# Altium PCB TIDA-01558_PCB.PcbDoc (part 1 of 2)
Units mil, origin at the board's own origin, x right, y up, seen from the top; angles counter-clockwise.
Board outline 2362.2 x 2362.2 mil, 2 copper layers (Top Layer, Bottom Layer), stack 64.8 mil thick; 83 components, 39 nets, 200 pads, 58 vias.
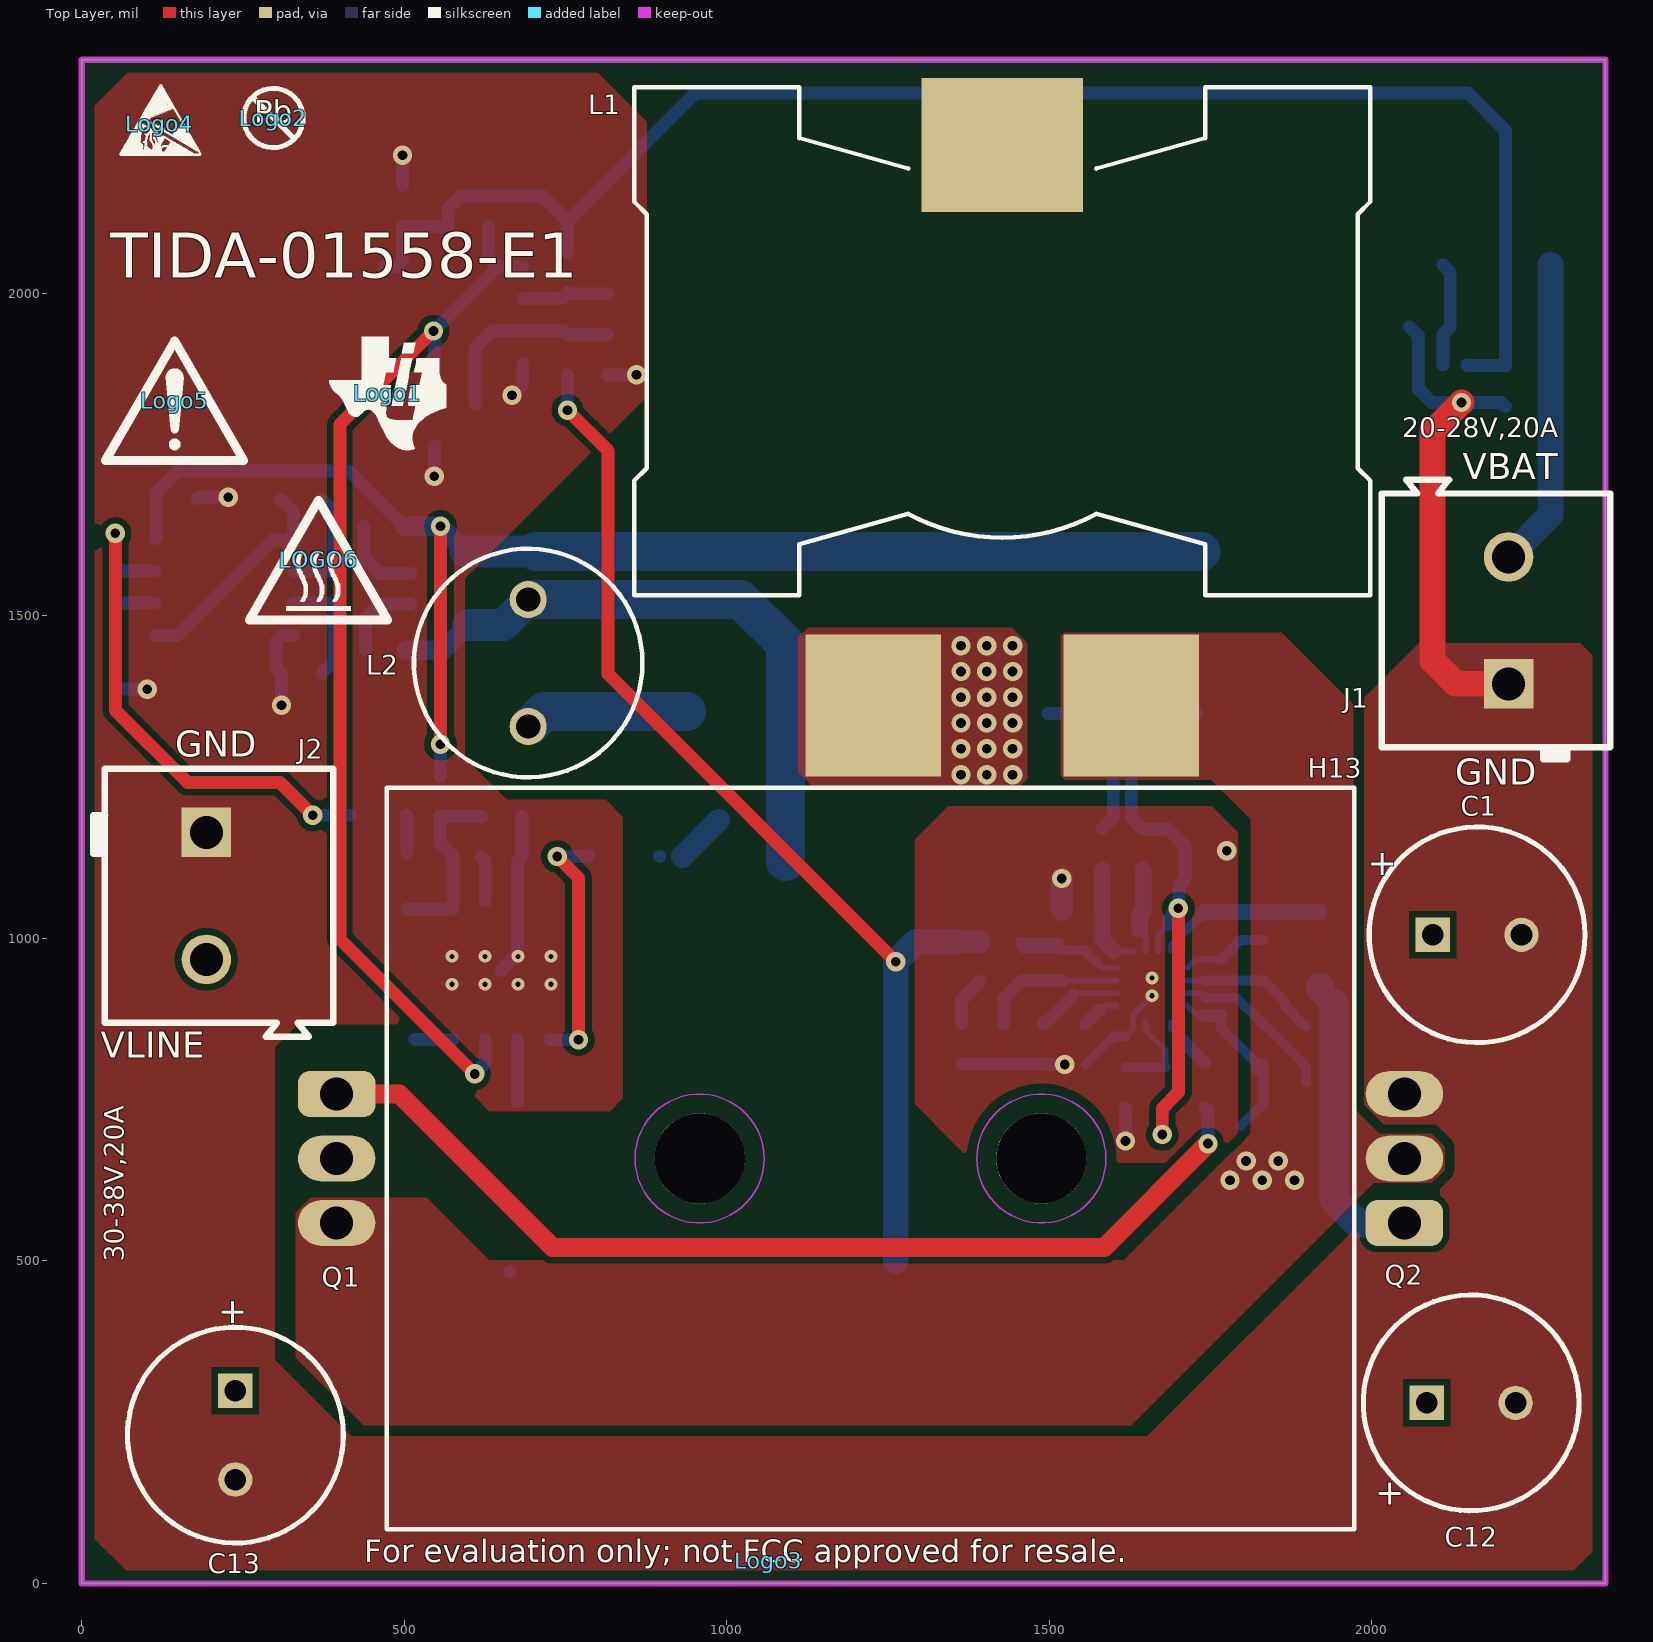
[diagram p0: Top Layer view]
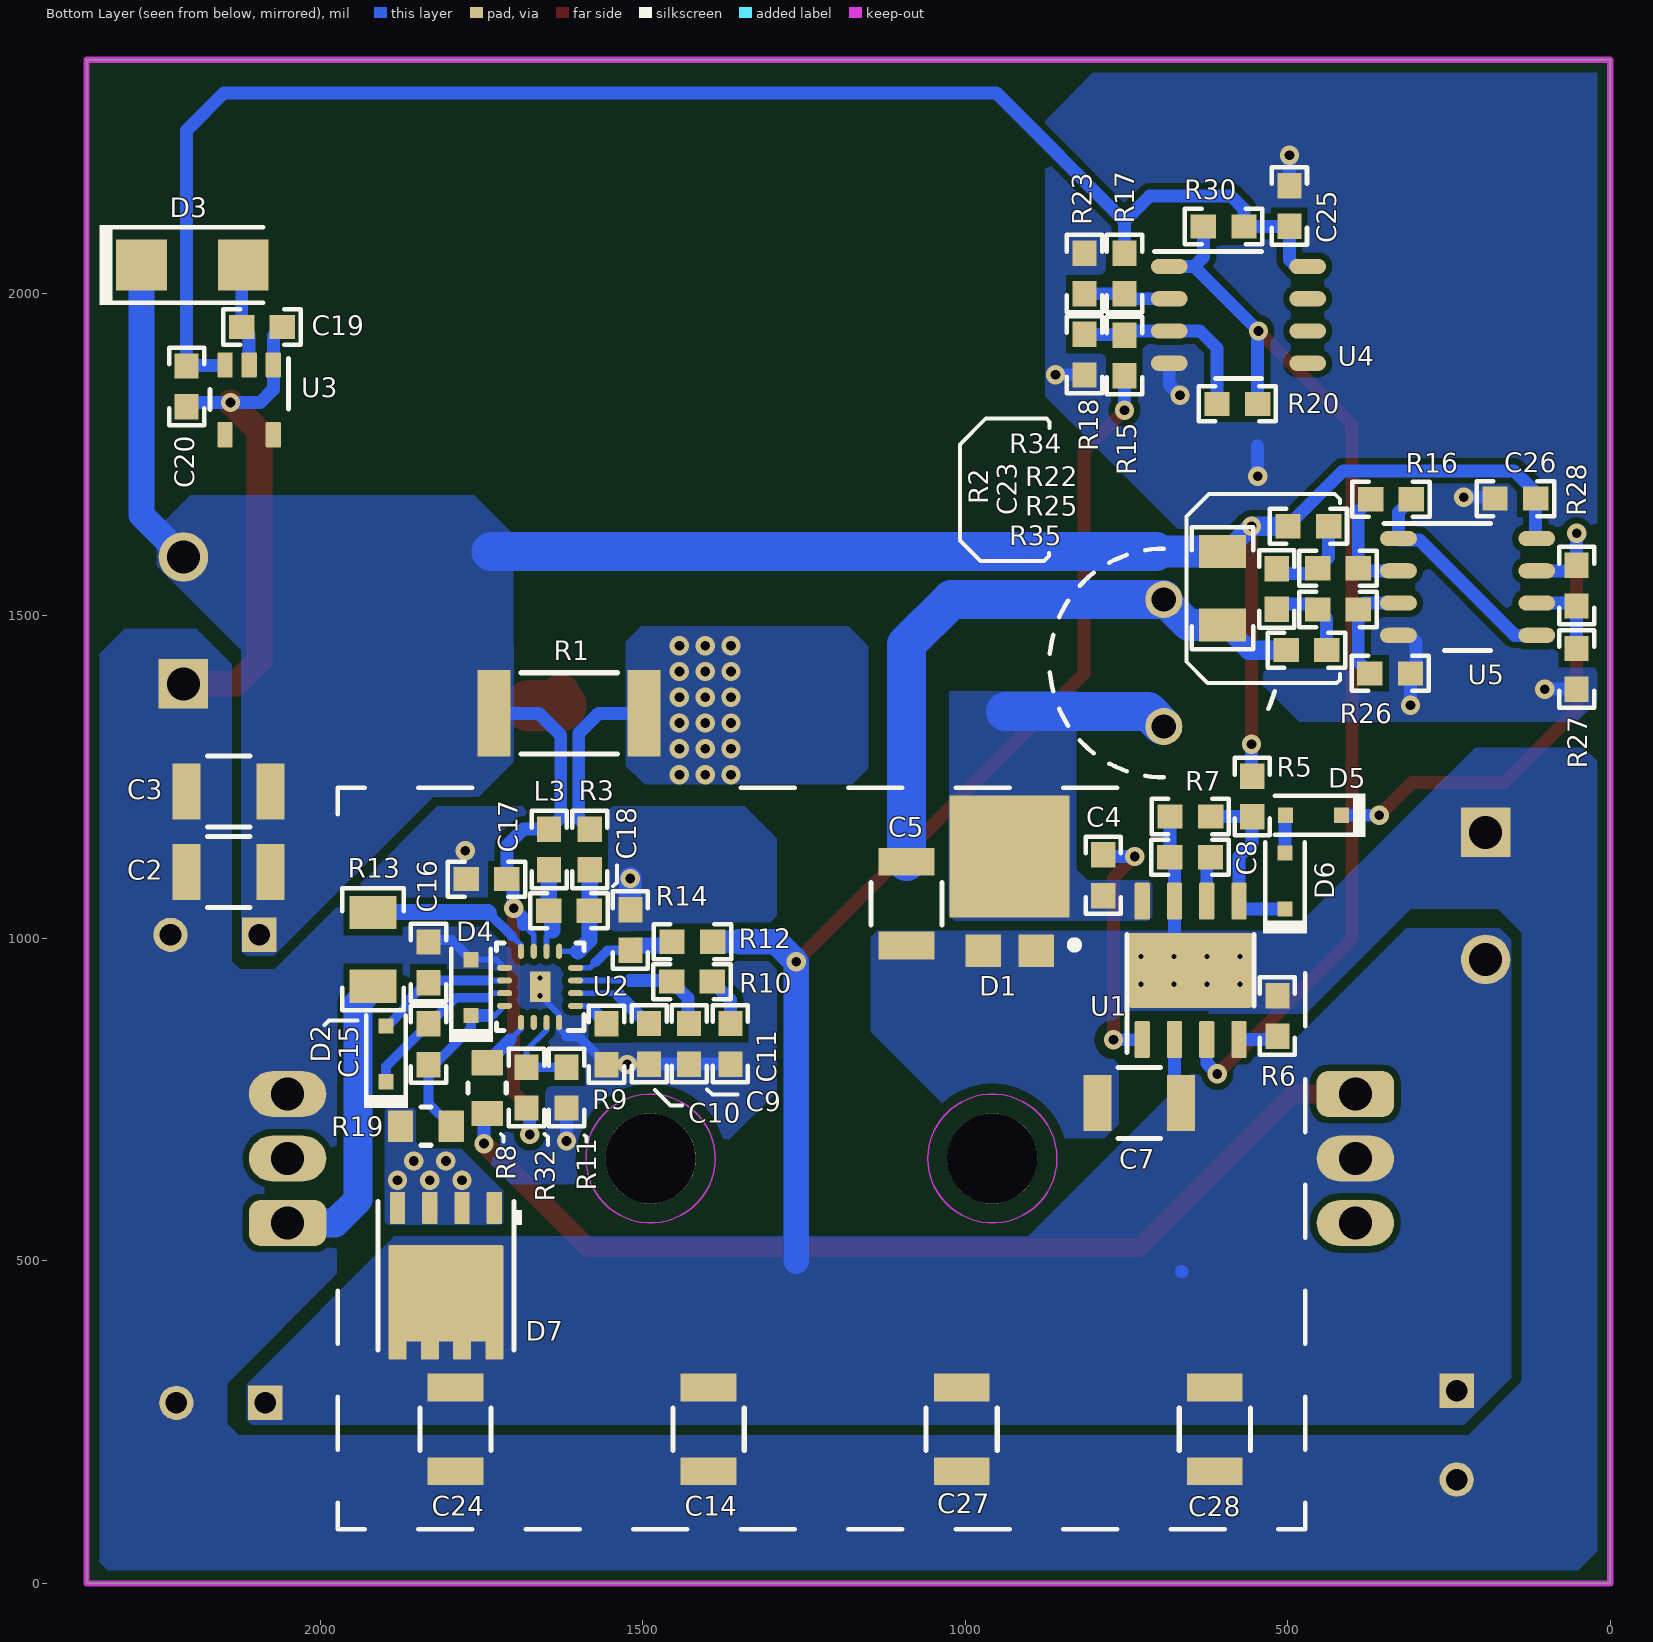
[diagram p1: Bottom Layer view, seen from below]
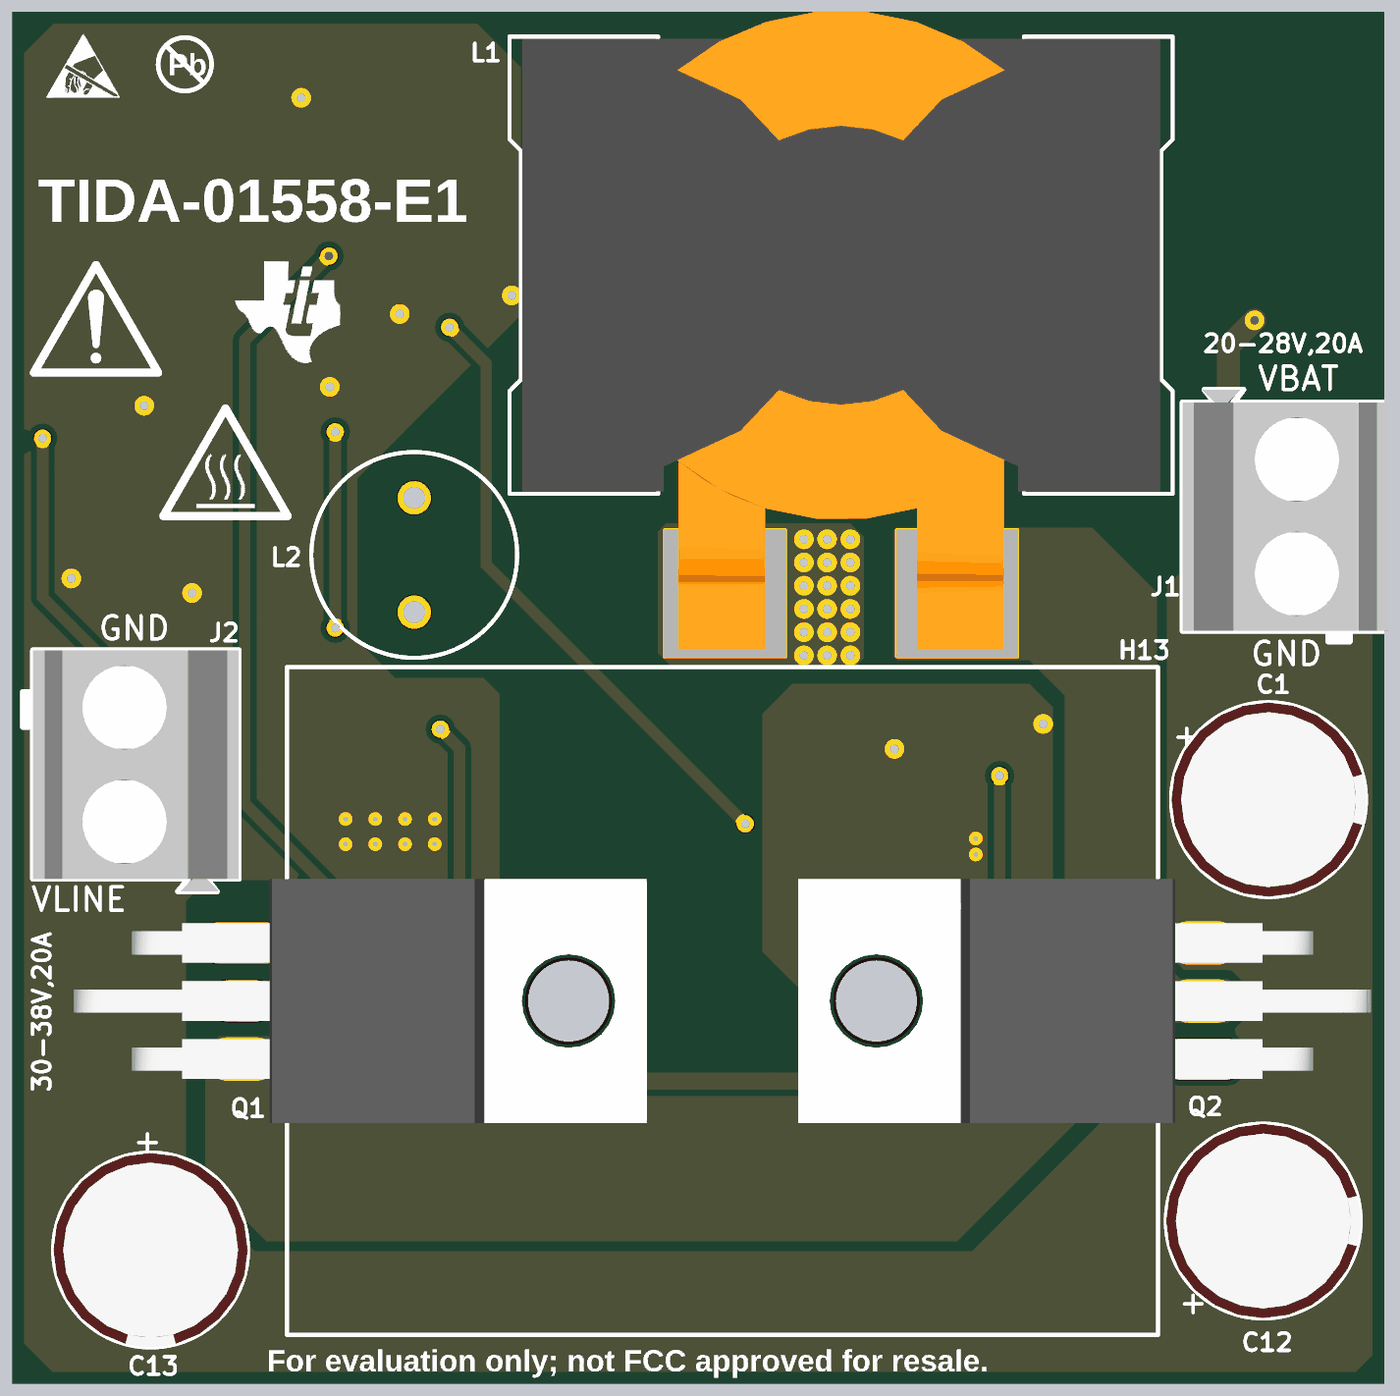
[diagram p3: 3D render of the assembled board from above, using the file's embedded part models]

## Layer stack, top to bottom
Top Solder: solder mask 0.4, Solder Resist, Dk 3.5
Top Layer: signal copper 2.8
Dielectric1: core 59.2, FR-4 High Tg, Dk 4.8
Bottom Layer: signal copper 2.8
Bottom Solder: solder mask 0.4, Solder Resist, Dk 3.5

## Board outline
0,0 0,2362.2 2362.2,2362.2 2362.2,0

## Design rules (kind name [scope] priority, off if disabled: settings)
AcuteAngle [All] p1: minimum=4.50000000000000E+0001 checktracksonly=FALSE
AssemblyTestPointUsage [All] p1: valid=2
Clearance Clearance_Keepouts [((IsTrack Or IsArc) And Not InPoly) And IsFree and IsKeepOut vs ((IsTrack Or IsArc) And Not InPoly) And IsFree and IsKeepOut] p1: gap=590.55 ignorepadtopadclearanceinfootprint=FALSE except(0: Arc-Hole Track-Hole SMDPad-Hole THPad-Hole Via-Hole Fill-Hole Poly-Hole Region-Hole Text-Hole)
Clearance Clearance_BoardEdge_MountingHoles [OnCopper and InComponentClass('Mounting Holes') vs IsKeepOut] p2: gap=40 ignorepadtopadclearanceinfootprint=FALSE except(0: Arc-Hole Track-Hole SMDPad-Hole THPad-Hole Via-Hole Fill-Hole Poly-Hole Region-Hole Text-Hole)
Clearance Clearance_BoardEdge_Poly [OnCopper and InPoly vs IsKeepOut] p3: gap=15 ignorepadtopadclearanceinfootprint=FALSE except(0: Arc-Hole Track-Hole SMDPad-Hole THPad-Hole Via-Hole Fill-Hole Poly-Hole Region-Hole Text-Hole)
Clearance Clearance_BoardEdge [OnCopper and Not InComponentClass('Logo') and not InComponentClass('FiducialMark') and not InRegion(1000,500,4000,800) and Not IsKeepout vs IsKeepOut] p4: gap=15 ignorepadtopadclearanceinfootprint=FALSE except(0: Arc-Hole Track-Hole SMDPad-Hole THPad-Hole Via-Hole Fill-Hole Poly-Hole Region-Hole Text-Hole)
Clearance Clearance_Poly [InPolygon] p5: gap=10 ignorepadtopadclearanceinfootprint=FALSE except(0: Arc-Hole Track-Hole SMDPad-Hole THPad-Hole Via-Hole Fill-Hole Poly-Hole Region-Hole Text-Hole; 15: Poly-Poly)
Clearance [All] p6: gap=7.87 ignorepadtopadclearanceinfootprint=FALSE except(0: Arc-Hole Track-Hole SMDPad-Hole THPad-Hole Via-Hole Fill-Hole Poly-Hole Region-Hole Text-Hole)
ComponentClearance ComponentClearance_MountingHoles_FiducialMarks [InComponentClass('Mounting Holes') vs InComponentClass('FiducialMark')] p1: gap=50 collisioncheckmode=3 verticalgap=10 showdistances=FALSE
ComponentClearance ComponentClearance_Shunt [InComponentClass('Header') vs InComponentClass('Shunt')] p2: gap=0 collisioncheckmode=3 verticalgap=0 showdistances=FALSE
ComponentClearance ComponentClearance_Logo [InComponentClass('Logo')] p3: gap=50 collisioncheckmode=3 verticalgap=10 showdistances=FALSE
ComponentClearance ComponentClearance_ScrewToNut [(HasFootprint('NY PMS 440 0025 PH')) vs (HasFootprint('Keystone_1902C'))] p4: gap=5 collisioncheckmode=3 verticalgap=10 showdistances=FALSE
ComponentClearance ComponentClearance_MountingHoles [InComponentClass('Mounting Holes')] p5: gap=250 collisioncheckmode=3 verticalgap=100000 showdistances=FALSE
ComponentClearance ComponentClearance_SmallPassives [HasFootprint('0201*') or HasFootprint('0402*') or HasFootprint('0508') or HasFootprint('0603*') or HasFootprint('0612') or HasFootprint('0805*') or HasFootprint('0815*') or HasFootprint('0830*') or HasFootprint('1206*') or HasFootprint('1210*') or HasFootprint('1808*') or HasFootprint('1812*') or HasFootprint('1825*') or HasFootprint('2010*') or HasFootprint('2220*') or HasFootprint('2225*') or HasFootprint('2512*') or HasFootprint('2728*') or HasFootprint('3518*') vs HasFootprint('0201*') or HasFootprint('0402*') or HasFootprint('0508') or HasFootprint('0603*') or HasFootprint('0612') or HasFootprint('0805*') or HasFootprint('0815*') or HasFootprint('0830*') or HasFootprint('1206*') or HasFootprint('1210*') or HasFootprint('1808*') or HasFootprint('1812*') or HasFootprint('1825*') or HasFootprint('2010*') or HasFootprint('2220*') or HasFootprint('2225*') or HasFootprint('2512*') or HasFootprint('2728*') or HasFootprint('3518*')] p6: gap=10 collisioncheckmode=3 verticalgap=10 showdistances=FALSE
ComponentClearance ComponentClearance_THtoSMT [IsThruComponent vs IsSMTComponent] p7: gap=10 collisioncheckmode=3 verticalgap=10 showdistances=FALSE
ComponentClearance ComponentClearance_THtoTH [IsThruComponent vs IsThruComponent] p8: gap=10 collisioncheckmode=3 verticalgap=10 showdistances=FALSE
ComponentClearance [All] p9: gap=10 collisioncheckmode=3 verticalgap=10 showdistances=FALSE
DiffPairsRouting [All] p1: maxlimit=100 minlimit=10 mostfreqgap=10 toplayer_minwidth=15 toplayer_maxwidth=15 toplayer_prefwidth=15 bottomlayer_minwidth=15 bottomlayer_maxwidth=15 bottomlayer_prefwidth=15 maxuncoupledlength=1000
FabricationTestPointUsage TestPointUsage [All] p1: valid=2 allowmultiple=FALSE
FabricationTestpoint Testpoint [All] p1: side=3 testpointundercomponent=TRUE minsize=40 maxsize=100 preferedsize=60 minholesize=0 maxholesize=40 preferedholesize=32 testpointgrid=1 allowsidetop=TRUE allowsidebottom=TRUE usegrid=TRUE gridtolerance=0.01
FanoutControl Fanout_LCC [IsLCC] p1: bgadir=Out bgaviamode=Centered fanoutstyle=Auto fanoutdirection=Alternating viagrid=1 // Fanout_LCC (Default Rule)
FanoutControl Fanout_BGA [IsBGA] p2: bgadir=Out bgaviamode=Centered fanoutstyle=Auto fanoutdirection=Alternating viagrid=1 // Fanout_BGA (Default Rule)
FanoutControl Fanout_Default [All] p4: bgadir=Out bgaviamode=Centered fanoutstyle=Auto fanoutdirection=Alternating viagrid=1 // Fanout_Default (Default Rule)
FanoutControl Fanout_Small [(CompPinCount < 5)] p5: bgadir=Out bgaviamode=Centered fanoutstyle=Auto fanoutdirection=OutThenIn viagrid=1 // Fanout_Small (Default Rule)
HoleSize [All] p1: absolutevalues=TRUE maxlimit=251 minlimit=7.87 maxpercent=80.000 minpercent=20.000
MinimumAnnularRing MinimumAnnularRing_ThermalPadVias [IsVia and InAnyComponent] p1: minimumring=5.91
MinimumAnnularRing [All] p2: minimumring=6
MinimumSolderMaskSliver MinimumSolderMaskSliver_Logo [InComponentClass('Logo') vs InComponentClass('Logo')] p1: minsoldermaskwidth=0.7
MinimumSolderMaskSliver [All] p2: minsoldermaskwidth=3.94
PlaneConnect [All] p1: planeconnectstyle=Relief reliefexpansion=10 reliefentries=4 reliefconductorwidth=10 reliefairgap=10
PolygonConnect [All] p1: connectstyle=Direct reliefconductorwidth=10 reliefentries=4 polygonreliefangle="90 Angle" airgapwidth=10
RoutingVias ThermalPadVias [IsVia and InAnyComponent] p1: holewidth=7.87 width=19.68 viastyle="Through Hole" minholewidth=7.87 minwidth=19.68 maxholewidth=12.99 maxwidth=23.62
RoutingVias [All] p2: holewidth=16 width=34 viastyle="Through Hole" minholewidth=7.87 minwidth=26 maxholewidth=40 maxwidth=65
SilkToBoardRegionClearance [Not ((IsComment or IsDesignator) And (Hide <> 'False')) and not InRegion(1000,500,4000,800)] p1:
SilkToSilkClearance SilkToSilkClearance_Pb-FreeLogo [(HasFootprint('Pb-Free_Overlay_Medium') OR HasFootprint('Pb-Free_Overlay_Small')) vs (HasFootprint('Pb-Free_Overlay_Medium') OR HasFootprint('Pb-Free_Overlay_Small'))] p1: silktosilkclearance=0
SilkToSilkClearance [All] p2: silktosilkclearance=4
SilkToSolderMaskClearance SilkToComonentPadClearance [IsPad and InAnycomponent] p1: minsilkscreentomaskgap=5 clearancetoexposedcopper=TRUE
SilkToSolderMaskClearance "Silk to Solder Mask Opening" [All] p2: minsilkscreentomaskgap=4 clearancetoexposedcopper=FALSE
SolderMaskExpansion [All] p1: expansion=1.97
Width [All] p1: maxlimit=100 minlimit=6 preferedwidth=10 checkconnectedcopper=TRUE
15 further rules are at their usual default settings.

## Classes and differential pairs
component class Logo: Logo1
component class TIDA-01558_Hardware: Logo1 Logo2 Logo3 Logo4 Logo5 LOGO6 ZZ2 ZZ3 ZZ4
component class AssemblyNote: ZZ2 ZZ3 ZZ4
component class TIDA-01558_Sheet1: C1 C2 C3 C4 C5 C7 C8 C9 C10 C11 C12 C13 C14 C15 C16 C17 C18 C19 C20 C23 C24 C25 C26 C27 C28 D1 D2 D3 D4 D5 D6 D7 H13 J1 J2 L1 L2 L3 Q1 Q2 R1 R2 R3 R5 R6 R7 R8 R9 R10 R11 R12 R13 R14 R15 R16 R17 R18 R19 R20 R22 R23 R25 R26 R27 R28 R30 R32 R34 R35 U1 U2 U3 U4 U5

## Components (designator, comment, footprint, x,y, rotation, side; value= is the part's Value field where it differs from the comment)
C1 "127AVG050MFBJ" Chemi-Con_800x1150 2163.13,1005.68 r0 top value=120uF
C2 "C3225X7R1H106M250AC" 1210_280 2142,1103 r0 bottom value=10uF
C3 "C3225X7R1H106M250AC" 1210_280 2142,1228 r0 bottom value=10uF
C4 "06033D224KAT2A" 0603 786,1098 r270 bottom value=0.22uF
C5 "C3225X7R1H106M250AC" 1210_280 1091,1054 r270 bottom value=10uF
C7 "C3225X7R1H106M250AC" 1210_280 730,745 r0 bottom value=10uF
C8 "GRM188R71E472KA01D" 0603 651.2,1126 r0 bottom value=4700pF
C9 "C0603C471K3RACTU" 0603 1428,836.73 r270 bottom value=470pF
C10 "06035A391JAT2A" 0603 1490,836.73 r270 bottom value=390pF
C11 "06033C473JAT2A" 0603 1364,836.73 r270 bottom value=0.047uF
C12 "127AVG050MFBJ" Chemi-Con_800x1150 2154,280 r0 top value=120uF
C13 "127AVG050MFBJ" Chemi-Con_800x1150 238,230 r270 top value=120uF
C14 "C3225X7R1H106M250AC" 1210_280 1397.67,239 r270 bottom value=10uF
C15 "06033D224KAT2A" 0603 1831.93,836 r90 bottom value=0.22uF
C16 "06033C105KAT2A" 0603 1832,963 r270 bottom value=1uF
C17 "06035C104KAT2A" 0603 1742,1092 r0 bottom value=0.1uF
C18 "GRM188R71E682KA01D" 0603 1614,1043 r180 bottom value=6800pF
C19 "06035C104KAT2A" 0603 2090,1948 r180 bottom value=0.1uF
C20 "06033C105KAT2A" 0603 2207,1856 r270 bottom value=1uF
C23 "GRM188R71E474KA12D" 0603 517,1542 r270 bottom value=0.47uF
C24 "C3225X7R1H106M250AC" 1210_280 1790,239 r270 bottom value=10uF
C25 "06033C104KAT2A" 0603 497.22,2135.77 r90 bottom value=0.1uF
C26 "06033C104KAT2A" 0603 147,1682 r0 bottom value=0.1uF
C27 "C3225X7R1H106M250AC" 1210_280 1005.33,239 r270 bottom value=10uF
C28 "C3225X7R1H106M250AC" 1210_280 613,239 r270 bottom value=10uF
D1 "MBR10U60-TP" TO-277A 931,1053 r0 bottom value=60V
D2 "PMEG6010CEJ,115" SOD-323F 1898,821 r90 bottom value=60V
D3 "SMAJ5922B-TP" SMA 2198,2044 r180 bottom value=7.5V
D4 "PMEG6010CEJ,115" SOD-323F 1766,923.69 r90 bottom value=60V
D5 "MMSZ5238BS-7-F" SOD-323 460,1191 r0 bottom value=8.7V
D6 "1N4448WX-TP" SOD-323 504,1089 r90 bottom value=75V
D7 "TSN520M60 S3G" PDFN56 1805,477 r270 bottom value=60V
H13 "7-345-2PP-BA" HEATSINK_7-340-2PP 1222.78,658.88 r0 top locked
J1 "691134710002" 691134710002 2212,1493 r90 top
J2 "691134710002" 691134710002 193,1066 r270 top
L1 "SER2915H-682KL" SER2915 1427,1926 r90 top value=6.8uH
L2 "RLB9012-180KL" IND_RLB9012 692,1427 r90 top value=18uH
L3 "BLM18KG601SN1D" 0603 1645,1138 r90 bottom value="600 ohm"
Logo1 "Texas Instruments" TI_Symbol_Overlay_Small 474,1845 r0 top
Logo2 "Pb-Free Symbol" Pb-Free_Overlay_Small 297,2272 r0 top
Logo3 "FCC disclaimer" FCC_disclaimer 1065,35 r0 top
Logo4 "ESD Susceptible" ESD_Overlay_Small 121,2263 r0 top
Logo5 "CAUTION.  READ USER GUIDE BEFORE USE" IEC_Caution_Small 144,1834 r0 top
LOGO6 "CAUTION HOT SURFACE" IEC_HotSurface_Small 367,1587 r0 top
Q1 "CSD18532KCS" TO-220AB_HORIZONTAL_100MIL 218.02,758.88 r270 top value=60V
Q2 "CSD18532KCS" TO-220AB_HORIZONTAL_100MIL 2227.55,558.89 r90 top locked value=60V
R1 "CRE2512-FZ-R002E-3" 2512 1614,1349 r180 bottom value=0.002
R2 "CRM1206-FX-R100ELF" 1206 601,1543 r90 bottom value=0.1
R3 "CRCW060320R0FKEA" 0603 1582,1138 r90 bottom value=20.0
R5 "RT0603BRD07309KL" 0603 555,1220 r90 bottom value=309k
R6 "RT0603BRD0726K7L" 0603 516,880 r270 bottom value=26.7k
R7 "CRCW060310K0FKEA" 0603 651,1189 r180 bottom value=10.0k
R8 "RC0805FR-072R2L" 0805_HV1 1741,768 r270 bottom value=2.20
R9 "RT0603BRD07287KL" 0603 1556,836 r90 bottom value=287k
R10 "RT0603DRE076K9L" 0603 1423.5,933 r0 bottom value=6.90k
R11 "ERJ-3EKF1002V" 0603 1618,768.73 r90 bottom value=10.0k
R12 "RT0603BRD07237KL" 0603 1423,995 r180 bottom value=237k
R13 "ERJ-8RQF2R2V" 1206 1918,983 r270 bottom value=2.20
R14 "CRCW060310K0FKEA" 0603 1519,1013 r270 bottom value=10.0k
R15 "CRCW0603110KFKEA" 0603 753,1904 r270 bottom value=110k
R16 "CRCW060315K0FKEA" 0603 340,1681 r180 bottom value=15.0k
R17 "ERJ-3EKF1002V" 0603 753,2031 r90 bottom value=10.0k
R18 "ERJ-3EKF1002V" 0603 815,1905 r90 bottom value=10.0k
R19 "CRCW08052R00FKEA" 0805_HV1 1836,709 r0 bottom value=2.00
R20 "RT0603BRD07147KL" 0603 578.09,1828.82 r180 bottom value=147k
R22 "CRCW06031K50FKEA" 0603 422,1574 r180 bottom value=1.50k
R23 "RT0603BRD0710K7L" 0603 815.07,2031 r270 bottom value=10.7k
R25 "CRCW06031K50FKEA" 0603 422,1510 r180 bottom value=1.50k
R26 "CRCW060315K0FKEA" 0603 341,1411 r0 bottom value=15.0k
R27 "CRCW06032K00FKEA" 0603 52,1418 r90 bottom value=2.00k
R28 "CRCW060315K0FKEA" 0603 52,1547 r270 bottom value=15.0k
R30 "RT0603BRD075K05L" 0603 599.22,2103.77 r0 bottom value=5.05k
R32 "CRCW06030000Z0EA" 0603 1680,768.73 r90 bottom value=0
R34 "CRCW06031K50FKEA" 0603 468,1639 r180 bottom value=1.50k
R35 "CRCW06031K50FKEA" 0603 471,1447 r180 bottom value=1.50k
U1 "LMR14020SDDAR" DDA0008E_N 650.52,950.63 r90 bottom
U2 "TPS43060RTER" RTE0016E 1659,925 r0 bottom
U3 "TLV70450DBVT" DBV0005A_N 2110,1835 r270 bottom
U4 "LM293AD" D0008A_N 576.24,1966.86 r180 bottom
U5 "LM358AD" D0008A_N 221,1545 r180 bottom
ZZ2 "These assemblies are ESD sensitive, ESD precautions shall be observed." AssemblyNote -121,3439.11 r0 top
ZZ3 "These assemblies must be clean and free from flux and all contaminants. Use of no clean flux is not acceptable." AssemblyNote -121,3350.56 r0 top
ZZ4 "These assemblies must comply with workmanship standards IPC-A-610 Class 2, unless otherwise specified." AssemblyNote -121,3262 r0 top

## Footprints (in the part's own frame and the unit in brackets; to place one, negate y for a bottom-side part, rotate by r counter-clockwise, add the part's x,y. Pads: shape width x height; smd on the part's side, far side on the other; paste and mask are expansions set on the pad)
0603 [mm] "0603 from SM-752 data"
  rect 1x0.95 smd: 1(-0.8,0) 2(0.8,0)
  silkscreen extent -1.52,-0.69 1.52,0.69, body extent -0.87,-0.47 0.87,0.47, height 1
0805_HV1 [mm] "Custom footprint based on analyzing multiple manufacturer recommendations"
  rrect10% 1x1.25 smd: 1(-1,0) 2(1,0)
  silkscreen extent -0.2,-0.75 0.2,0.75, body extent -1.1,-0.72 1.1,0.73, height 1.45
1206 [mm] "1206 from SM-752 data"
  rect 1.3x1.85 smd: 1(-1.45,0) 2(1.45,0)
  silkscreen extent -2.4,-1.21 2.4,1.21, body extent -1.7,-0.9 1.7,0.9, height 1.35
1210_280 [mm] "SMD, 2-Leads, Body 3.6x2.8mm, Height 2.8mm"
  rect 1.1x2.2 smd: 1(-1.65,0) 2(1.65,0)
  silkscreen extent -0.84,-1.4 0.84,1.4, body extent -1.8,-1.4 1.8,1.4, height 2.8
2512 [mm] "Chip Resistor, Body 6.3x3.2mm, IPC Medium Density"
  rect 1.3x3.4 smd: 1(-2.95,0) 2(2.95,0)
  silkscreen extent -1.9,-1.6 1.9,1.6, body extent -3.22,-1.67 3.22,1.67, height 0.71
691134710002 [mm] "Serie 1347 - 5.00 mm_2 pins"
  rect 1.95x1.95 hole 1.3: 1(-2.5,0)
  round 1.95 hole 1.3: 2(2.5,0)
  silkscreen extent -5,-4 5.55,5, body extent -5,-4 5.55,5, height 13.1
AssemblyNote [mil] "Assembly Note"
Chemi-Con_800x1150 [mm] "TH, 2-Leads, Dia 8mm"
  rect 1.35x1.35 hole 0.85: 1(-1.75,0)
  round 1.35 hole 0.85: 2(1.75,0)
  silkscreen extent -4.25,-4.25 4.25,4.25, body extent -4.22,-4.24 4.24,4.24, height 13.01
D0008A_N [mm] "SOIC, 8-Leads, Body 4.9x3.9mm, Pitch 1.27mm, IPC Medium Density"
  oval 1.45x0.6 smd: 1(-2.725,1.905) 2(-2.725,0.635) 3(-2.725,-0.635) 4(-2.725,-1.905) 5(2.725,-1.905) 6(2.725,-0.635) 7(2.725,0.635) 8(2.725,1.905)
  silkscreen extent -3.3,-2.5 0.9,2.5, body extent -3,-2.45 3,2.45, height 1.63
DBV0005A_N [mm] "SOT23, 5-Leads, Body 2.9x1.6mm, Pitch 0.95mm, Lead Span 2.8mm, IPC Medium Density"
  rrect17% 1x0.6 smd: 1(-1.375,0.95) 2(-1.375,0) 3(-1.375,-0.95) 4(1.375,-0.95) 5(1.375,0.95)
  silkscreen extent -1.63,-1.55 0.38,1.55, body extent -1.42,-1.46 1.42,1.46, height 1.09
DDA0008E_N [mm]
  rrect17% 1.45x0.6 smd: 1(-2.725,1.905) 2(-2.725,0.635) 3(-2.725,-0.635) 4(-2.725,-1.905) 5(2.725,-1.905) 6(2.725,-0.635) 7(2.725,0.635) 8(2.725,1.905)
  rrect7% 2.95x4.9 smd: 9(0,0)
  rrect50% 2.4x3.1 on Bottom Paste: 9(0,0)
  rrect50% 2.4x3.1 on Bottom Solder: 9(0,0)
  silkscreen extent -3.22,-2.5 1.4,2.5, body extent -3,-2.45 3,2.45, height 1.57
ESD_Overlay_Small [mil]
  silkscreen extent -62,-48 64,61
FCC_disclaimer [mil]
HEATSINK_7-340-2PP [mil] "HEATSINK, DUAL TO-220"
  round 140 hole 140 unplated mask+5: ""(-265,0) ""(265,0)
  Keep-Out Layer circle w1.97: c265,0 r100
  Keep-Out Layer circle w1.97: c-265,0 r100
  silkscreen extent -750,-575 750,575, body extent -750,-575 750,575, height 460
IEC_Caution_Small [mil]
  silkscreen extent -107,-93 107,92
IEC_HotSurface_Small [mil]
  silkscreen extent -107,-93 107,92
IND_RLB9012 [mm] "INDUCTOR, RLB9012 SERIES, 2-PIN"
  round 1.462 hole 0.954: 1(-2.5,0) 2(2.5,0)
  silkscreen extent -4.5,-4.5 4.5,4.5, body extent -4.5,-4.5 4.5,4.5, height 12.2
Pb-Free_Overlay_Small [mil]
  silkscreen extent -46,-46 46,46
PDFN56 [mm] "SMD, 8-Leads, Body 5.7x5.2mm"
  rrect17% 1.27x0.6 smd: 1(-2.67,1.905) 2(-2.67,0.635) 3(-2.67,-0.635) 4(-2.67,-1.905)
  rrect14% 0.81x0.71 smd: 5(2.9,-1.905) 6(2.9,-0.635) 7(2.9,0.635) 8(2.9,1.905)
  rrect3% 3.81x4.52 smd: 9(0.69,0)
  silkscreen extent -2.93,-2.68 2.93,3, body extent -2.93,-2.68 2.93,2.68, height 1.25
RTE0016E [mm] "Texas Insturments"
  oval 0.6x0.24 smd paste+0: 1(-1.4,0.75) 2(-1.4,0.25) 3(-1.4,-0.25) 4(-1.4,-0.75) 9(1.4,-0.75) 10(1.4,-0.25) 11(1.4,0.25) 12(1.4,0.75)
  oval 0.24x0.6 smd paste+0: 5(-0.75,-1.4) 6(-0.25,-1.4) 7(0.25,-1.4) 8(0.75,-1.4) 13(0.75,1.4) 14(0.25,1.4) 15(-0.25,1.4) 16(-0.75,1.4)
  rect 0.8x1.2 smd paste-1: 17(0,0)
  silkscreen extent -1.73,-1.73 1.73,1.73, body extent -1.58,-1.58 1.58,1.58, height 0.81
SER2915 [mm] "Coilcraft recommended land pattern.  Document 644-2, rev 12/12/08"
  rect 5.59x5.33 smd: 1(-14.355,5.075) 2(-14.355,-5.075)
  rect 5.28x6.35 smd: 3(7.72,0)
  silkscreen extent -10,-14.5 10,14.5, body extent -16.8,-13.95 11.03,13.95, height 15.36
SMA [mm] "Molded Diode, 2-Leads, Body 4.3x2.6mm, IPC Medium Density, based on OnSemi component dimensions and land pattern"
  rect 2x2 smd: 1(-2,0) 2(2,0)
  silkscreen extent -3.66,-1.57 2.79,1.57, body extent -2.6,-1.3 2.6,1.3, height 2.42
SOD-323 [mm] "NXP recommended land pattern"
  rect 0.6x0.6 smd paste-0.05: 1(-1.1,0) 2(1.1,0)
  silkscreen extent -2.06,-0.86 1.53,0.86, body extent -1.3,-0.67 1.3,0.68, height 1.1
SOD-323F [mm] "NXP recommended land pattern"
  rect 0.6x0.6 smd paste-0.05: 1(-1.1,0) 2(1.1,0)
  silkscreen extent -2.13,-0.86 1.53,0.86, body extent -1.35,-0.68 1.35,0.67, height 0.79
TI_Symbol_Overlay_Small [mil]
  silkscreen extent -90,-88 91,88
TO-220AB_HORIZONTAL_100MIL [mm] "High Voltage staggered pins"
  rrect50% 1.8x3.048 hole 1.3: 1(0,4.5)
  rect 11x15 on Mech15: 2(2.54,14.732)
  oval 1.8x3.048 hole 1.3: 2(2.54,4.5) 3(5.08,4.5)
  body extent -2.8,-2.85 7.87,22.22, height 7.8
TO-277A [mm] "Vishay"
  rect 1.4x1.27 smd: 1(-1.04,1.83) 2(1.04,1.83)
  rect 4.72x4.8 smd: 3(0,-1.883)
  silkscreen extent -2.7,1.45 -2.4,1.75, body extent -2.35,-4.2 2.4,2.45, height 1.2

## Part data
C1 C12 C13: library part EKMG500ELL101MHB5D, "CAP, AL, 120 µF, 50 V, +/- 20%, TH", Cap_Case=8x11.5mm, Manufacturer="Illinois Capacitor", Supplier Part Number 1=1572-1332-ND, Tolerance_%=20, Value2=50V, ValueDisplayed=120µF
C2 C3 C5 C7 C14 C24 C27 C28: "CAP, CERM, 10 µF, 50 V,+/- 20%, X7R, 1210", Cap_Case=1210, Manufacturer=TDK, Supplier Part Number 1=445-14933-1-ND, TempCo=X7R, Tolerance_%=20, Value2=50V, ValueDisplayed=10µF
C4 C15: "CAP, CERM, 0.22 µF, 25 V,+/- 10%, X5R, 0603", Cap_Case=0603, Manufacturer=AVX, Supplier Part Number 1=478-1245-1-ND, TempCo=X5R, Tolerance_%=10, Value1="0.036 ohm", Value2=25V, ValueDisplayed=0.22µF
C8: "CAP, CERM, 4700 pF, 25 V,+/- 10%, X7R, 0603", Cap_Case=0603, Manufacturer=MuRata, Supplier Part Number 1=81-GRM39X472K25D, TempCo=X7R, Tolerance_%=10, Value2=25V, ValueDisplayed=4700pF
C9: library part C0603C471K5RACTU, "CAP, CERM, 470 pF, 25 V,+/- 10%, X7R, 0603", Cap_Case=0603, Manufacturer=Kemet, Supplier Part Number 1=399-9086-2-ND, TempCo=X7R, Tolerance_%=10, Value2=25V, ValueDisplayed=470pF
C10: "CAP, CERM, 390 pF, 50 V,+/- 5%, C0G/NP0, 0603", Cap_Case=0603, Manufacturer=AVX, Supplier Part Number 1=478-1182-1-ND, TempCo=C0G/NP0, Tolerance_%=5, Value1="0.067 ohm", Value2=50V, ValueDisplayed=390pF
C11: "CAP, CERM, 0.047 µF, 25 V,+/- 5%, X7R, 0603", Cap_Case=0603, Manufacturer=AVX, Supplier Part Number 1=478-3716-1-ND, TempCo=X7R, Tolerance_%=5, Value1="0.052 ohm", Value2=25V, ValueDisplayed=0.047µF
C16 C20: "CAP, CERM, 1 µF, 25 V,+/- 10%, X7R, 0603", Cap_Case=0603, Manufacturer=AVX, Supplier Part Number 1=478-10046-1-ND, TempCo=X7R, Tolerance_%=10, Value1=Unknown, Value2=25V, ValueDisplayed=1µF
C17 C19: "CAP, CERM, 0.1 µF, 50 V,+/- 10%, X7R, 0603", Cap_Case=0603, Manufacturer=AVX, Supplier Part Number 1=478-5052-1-ND, TempCo=X7R, Tolerance_%=10, Value2=50V, ValueDisplayed=0.1µF
C18: "CAP, CERM, 6800 pF, 25 V,+/- 10%, X7R, 0603", Cap_Case=0603, Manufacturer=MuRata, Supplier Part Number 1=81-GRM18R71E682KA01D, TempCo=X7R, Tolerance_%=10, Value2=25V, ValueDisplayed=6800pF
C23: "CAP, CERM, 0.47 µF, 25 V,+/- 10%, X7R, 0603", Cap_Case=0603, Manufacturer=MuRata, Supplier Part Number 1=490-3291-1-ND, TempCo=X7R, Tolerance_%=10, Value2=25V, ValueDisplayed=0.47µF
C25 C26: "CAP, CERM, 0.1 µF, 25 V,+/- 10%, X7R, 0603", Cap_Case=0603, Manufacturer=AVX, Supplier Part Number 1=478-3714-1-ND, TempCo=X7R, Tolerance_%=10, Value1="0.05 ohm", Value2=25V, ValueDisplayed=0.1µF
D1: library part FSV10100V, "DIODE SCHOTTKY 60V 10A TO277", Manufacturer="Micro Commercial Co", Supplier Part Number 1=MBR10U60-TPMSCT-ND, Value1=10A
D2 D4: "Diode, Schottky, 60 V, 1 A, SOD-323F", Manufacturer=Nexperia, Supplier Part Number 1=568-4138-1-ND, Value1=1A, Value2=0.66V
D3: library part SMAZ30-13-F, "DIODE ZENER 7.5V 1.5W DO214AC", Manufacturer="Micro Commercial Co", Power_W=1, Supplier Part Number 1=SMAJ5922BTPMSTR-ND, Value1=1.5W
D5: "Diode, Zener, 8.7 V, 200 mW, SOD-323", Manufacturer="Diodes Inc.", Power_W=0.2, Supplier Part Number 1=MMSZ5238BS-FDICT-ND, Value1=0.2W
D6: "Diode, Switching, 75 V, 0.25 A, SOD-323", Manufacturer="Micro Commercial Components", Supplier Part Number 1=1N4448WXTPMSCT-ND, Value1=0.25A, Value2=V
D7: library part CMP-0078759-1, "Diode, Schottky, 60 V, 20 A, AEC-Q101, PDFN56", Manufacturer="Taiwan Semiconductor", Supplier Part Number 1="TSN520M60 S3GCT-ND", Value1=20A, Value2=0.58V
H13: "Heatsink, TO-220, Black Anodized", Manufacturer="CTS Electrocomponents", Supplier Part Number 1=294-1082-ND
J1 J2: "WR-TBL Serie 1347 - 5.00 mm Horizontal Cable Entry with Pressure Clamp, 02p", Manufacturer="Wurth Elektronik"
L1: "Inductor, Shielded E Core, Ferrite, 6.8uH, 30A, 0.00186 ohm, SMD", Manufacturer=Coilcraft, Value1="0.00186 ohm", Value2=30A, ValueDisplayed=6.8µH
L2: "INDUCTOR, FIXED, 18uH, 10%, 2.66A, 11MHz, TH, 2-PIN", Manufacturer=BOURNS
L3: "Ferrite Bead, 600 ohm @ 100 MHz, 1.3 A, 0603", Manufacturer=MuRata, Supplier Part Number 1=490-5258-1-ND, Value1="0.15 ohm", Value2=1.3A, ValueDisplayed="600 ohm"
Logo1: library part TI_Logo, "Texas Instrument Corporate Signature"
Logo2: library part Pb-Free
Logo3: library part FCC_disclaimer, "FCC_disclaimer"
Logo4: library part ESD_Susceptible, "ESD Susceptible Symbol"
Logo5: library part IEC_Caution, "IEC 61010-1 Caution Warning"
LOGO6: library part IEC_HotSurface, "IEC 61010-1 Hot Surface Warning"
Q1 Q2: "MOSFET, N-CH, 60 V, 100 A, KCS0003B (TO-220-3)", Alternate Manufacturer=None, Manufacturer="Texas Instruments", Supplier Part Number 1=296-34941-5-ND, Value1="0.0053 ohm", Value2="44 nC"
R1: library part ERJ-M1WTF2M0U, "RES SMD 2 MOHM 1% 3W 2512", Manufacturer="Bourns Inc.", Power_W=1, Supplier Part Number 1=CRE2512-FZ-R002E-3CT-ND, TempCo=ppm/C, Value1=1%, Value2=3W, Value_Code=2L000, ValueDisplayed=0.002
R2: "RES, 0.1, 1%, 0.5 W, 1206", Manufacturer=Bourns, Power_W=0.5, Supplier Part Number 1=652-CRM1206FXR100ELF, TempCo="150 ppm/C", Tolerance_%=1, Value1=1%, Value2=0.5W, Value_Code=R100, ValueDisplayed=0.1
R3: "RES, 20.0, 1%, 0.1 W, 0603", Manufacturer=Vishay-Dale, Power_W=0.1, Supplier Part Number 1=541-20.0HCT-ND, TempCo="100 ppm/C", Tolerance_%=1, Value1=1%, Value2=0.1W, Value_Code=20R0, ValueDisplayed=20.0
R5: "RES, 309 k, 0.1%, 0.1 W, 0603", Manufacturer="Yageo America", Power_W=0.1, TempCo="25 ppm/C", Value1=0.1%, Value2=0.1W, Value_Code=309k
R6: "RES, 26.7 k, 0.1%, 0.1 W, 0603", Manufacturer="Yageo America", Power_W=0.1, TempCo="25 ppm/C", Value1=0.1%, Value2=0.1W, Value_Code=26k7, ValueDisplayed=26.7k
R7 R14: "RES, 10.0 k, 1%, 0.1 W, 0603", Manufacturer=Vishay-Dale, Power_W=0.1, Supplier Part Number 1=541-10.0KHCT-ND, TempCo="100 ppm/C", Tolerance_%=1, Value1=1%, Value2=0.1W, Value_Code=10k0, ValueDisplayed=10.0k
R8: "RES, 2.20, 1%, 0.125 W, 0805", Manufacturer="Yageo America", Power_W=0.125, Supplier Part Number 1=311-2.20CRCT-ND, TempCo="200 ppm/C", Tolerance_%=1, Value1=1%, Value2=0.125W, Value_Code=2R20, ValueDisplayed=2.20
R9: "RES, 287 k, 0.1%, 0.1 W, 0603", Manufacturer="Yageo America", Power_W=0.1, TempCo="25 ppm/C", Value1=0.1%, Value2=0.1W, Value_Code=287k
R10: "RES, 6.90 k, 0.5%, 0.1 W, 0603", Manufacturer="Yageo America", Power_W=0.1, TempCo="50 ppm/C", Tolerance_%=0.5, Value1=0.5%, Value2=0.1W, Value_Code=6k90, ValueDisplayed=6.90k
R11 R17 R18: "RES, 10.0 k, 1%, 0.1 W, 0603", Manufacturer=Panasonic, Power_W=0.1, Supplier Part Number 1=P10.0KHCT-ND, TempCo="100 ppm/C", Tolerance_%=1, Value1=1%, Value2=0.1W, Value_Code=10k0, ValueDisplayed=10.0k
R12: "RES, 237 k, 0.1%, 0.1 W, 0603", Manufacturer="Yageo America", Power_W=0.1, TempCo="25 ppm/C", Value1=0.1%, Value2=0.1W, Value_Code=237k
R13: "RES, 2.20, 1%, 0.25 W, 1206", Manufacturer=Panasonic, Power_W=0.25, Supplier Part Number 1=P2.2RCT-ND, TempCo="200 ppm/C", Tolerance_%=1, Value1=1%, Value2=0.25W, Value_Code=2R20, ValueDisplayed=2.20
R15: "RES, 110 k, 1%, 0.1 W, 0603", Manufacturer=Vishay-Dale, Power_W=0.1, Supplier Part Number 1=541-110KHCT-ND, TempCo="100 ppm/C", Tolerance_%=1, Value1=1%, Value2=0.1W, Value_Code=110k
R16 R26 R28: "RES, 15.0 k, 1%, 0.1 W, 0603", Manufacturer=Vishay-Dale, Power_W=0.1, Supplier Part Number 1=541-15.0KHCT-ND, TempCo="100 ppm/C", Tolerance_%=1, Value1=1%, Value2=0.1W, Value_Code=15k0, ValueDisplayed=15.0k
R19: "RES, 2.00, 1%, 0.125 W, 0805", Manufacturer=Vishay-Dale, Power_W=0.125, Supplier Part Number 1=541-2.00CCCT-ND, TempCo="100 ppm/C", Tolerance_%=1, Value1=1%, Value2=0.125W, Value_Code=2R00, ValueDisplayed=2.00
R20: "RES, 147 k, 0.1%, 0.1 W, 0603", Manufacturer="Yageo America", Power_W=0.1, TempCo="25 ppm/C", Value1=0.1%, Value2=0.1W, Value_Code=147k
R22 R25 R34 R35: "RES, 1.50 k, 1%, 0.1 W, 0603", Manufacturer=Vishay-Dale, Power_W=0.1, Supplier Part Number 1=541-1.50KHCT-ND, TempCo="100 ppm/C", Tolerance_%=1, Value1=1%, Value2=0.1W, Value_Code=1k50, ValueDisplayed=1.50k
R23: "RES, 10.7 k, 0.1%, 0.1 W, 0603", Manufacturer="Yageo America", Power_W=0.1, TempCo="25 ppm/C", Value1=0.1%, Value2=0.1W, Value_Code=10k7, ValueDisplayed=10.7k
R27: "RES, 2.00 k, 1%, 0.1 W, 0603", Manufacturer=Vishay-Dale, Power_W=0.1, Supplier Part Number 1=541-2.00KHCT-ND, TempCo="100 ppm/C", Tolerance_%=1, Value1=1%, Value2=0.1W, Value_Code=2k00, ValueDisplayed=2.00k
R30: "RES, 5.05 k, 0.1%, 0.1 W, 0603", Manufacturer="Yageo America", Power_W=0.1, TempCo="25 ppm/C", Value1=0.1%, Value2=0.1W, Value_Code=5k05, ValueDisplayed=5.05k
R32: "RES, 0, 5%, 0.1 W, 0603", Manufacturer=Vishay-Dale, Power_W=0.1, Supplier Part Number 1=541-0.0GCT-ND, TempCo="200 ppm/C", Tolerance_%=5, Value1=5%, Value2=0.1W, Value_Code=0000, ValueDisplayed=0
U1: "SIMPLE SWITCHER, 4V to 40V, 2A 2.2MHz Step-Down Regulator with Low IQ, DDA0008E (SOIC-8)", Alternate Manufacturer="Texas Instruments", Alternate PartNumber=LMR14020SDDA
U2: "Low Iq, Synchronous Boost Controller with Wide Input Voltage and 7.5V Gate Drive for Standard FETs, RTE0016E (WQFN-16)", Alternate Manufacturer="Texas Instruments", Alternate PartNumber=TPS43060RTET
U3: "Single Output LDO, 150 mA, Fixed 5 V Output, 2.5 to 24 V Input, with Ultra-Low IQ, 5-pin SOT-23 (DBV), -40 to 125 degC, Green (RoHS & no Sb/Br)", Alternate Manufacturer="Texas Instruments", Alternate PartNumber=Equivalent, Supplier Part Number 1=296-28171-2-ND
U4: "Dual Comparator, D0008A", Alternate Manufacturer="Texas Instruments"
U5: "Dual Low Power Op Amp, D0008A", Alternate Manufacturer="Texas Instruments"
ZZ2 ZZ3 ZZ4: library part AssemblyNote, Alternate Manufacturer=-

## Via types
v1: diameter 30, hole 15, Top Layer to Bottom Layer, 48 vias
v2: diameter 19.68, hole 7.87, Top Layer to Bottom Layer, 10 vias

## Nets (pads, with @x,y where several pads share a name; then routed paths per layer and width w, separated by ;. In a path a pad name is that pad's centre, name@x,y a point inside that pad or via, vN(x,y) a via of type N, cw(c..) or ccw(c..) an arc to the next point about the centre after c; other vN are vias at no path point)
A: C5.1 L2.2 R2.1 R35.1 | length 986.8
  Bottom Layer w30: R35.1@502.5,1447 560.09,1447 R2.1@599,1485.91
  Bottom Layer w50: R2.1@599,1485.91 R2.1@601,1485.91 653.49,1485.91 L2.2@693,1525.43
  Bottom Layer w60: L2.2@693,1525.43 1021.57,1525.43 1091,1456 C5.1@1091,1118.96
BUCK_EN: R20.2 R30.2 U1.3 U4.1 | length 1720.9
  Top Layer w20: v1(545.13,1941.86) 400,1796.72 400,999 v1(609,790)
  Bottom Layer w20: v1(545.13,1941.86) v1@546.59,1943.32 ; R20.2@546.59,1828.82 v1@546.59,1943.32 ; v1(609,790) 625.52,806.52 U1.3@625.52,843.34 ; R30.2@630.72,2103.77 630.72,2056.28 645.13,2041.86 ; U4.1@683.52,2041.86 645.13,2041.86 ; v1@546.59,1943.32 645.13,2041.86
BUCK_FB: D6.1 R5.1 R7.2 U1.5 | length 287.5
  Bottom Layer w20: D6.1@504,1045.69 575.52,1045.69 U1.5@575.52,1057.91 575.52,1127.48 555,1148 R5.1@555,1188.5 555.5,1189 R7.2@619.5,1189
FB: R12.1 R14.2 U2.4 | length 166.2
  Bottom Layer w9: 1573,963 1581.47,954.53 U2.4@1603.88,954.53
  Bottom Layer w15: R12.1@1454.5,995 R12.1@1460.5,989 ; R14.2@1511.5,989 R14.2@1519,981.5 1554.5,981.5 1573,963
  Bottom Layer w25: R12.1@1460.5,989 R14.2@1511.5,989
